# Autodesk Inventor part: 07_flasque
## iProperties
Shininess: 20.0
Length Units: 11270
Angle Units: 11279
Time Units: 11290
Mass Units: 11283
Length Display Precision: 3
Angle Display Precision: 2
Created: 2000-10
Part Number: 07_flasque
Material: Par défaut
Document SubType Name: Modélisation
Density: 0.0
Volumn: 0.0
Area: 0.0
PropertySet Name: Model Information
Control State: 0
Master: False
Checked Out: False
Author: Laurent GAUTHERON
